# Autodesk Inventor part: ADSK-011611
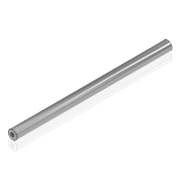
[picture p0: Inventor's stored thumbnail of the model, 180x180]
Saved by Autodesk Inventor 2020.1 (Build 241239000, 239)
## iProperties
Created: 2000-02
Part Number: ADSK-011611
Material: Pearson DGP
Document SubType Name: Modeling
Designer: sspink
Density: 7.83 g/cm^3
Appearance: Chrom - poliert
Mass: 1572.14 g
Surface Area: 359.989 cm^2
Volume: 200.785 cm^3
Control State: 0
Checked Out: False
Master: False
Shininess: 60.0
Length Units: 11269
Angle Units: 11279
Time Units: 11290
Mass Units: 11283
Length Display Precision: 3
Angle Display Precision: 2
Compacted: True
Cutlength: 23.25
Material Desc: Material Description goes here
Material_Number: Pearson
Dimensions: 25x420x25 mm
Mass: 1,572 kg
DocNumber: ADSK-011611.ipt
Folder: 01 - Themengebiete\Simplification\01 - Packaging machine\
VDS_Category: 3D Komponenten
VLT_Material: Pearson DGP
Density: 7.83
Volumn: 204.48056223073252
Area: 356.691416726128
PropertySet Name: Model Information
Author: sspink
Revision Number: -
Title: shaft
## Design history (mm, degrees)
node "Solide1"
  node "Extrusion1" dims "d1" = 420, "d2" = 0
  node "Hole1" dims "d3" = 10.106, "d4" = 9.525, "d5" = 6.35, "d6" = 60 deg, "d7" = 32.3, "d8" = 118 deg, "d21" = 24
  node "Hole2" dims "d9" = 10.106, "d10" = 9.525, "d11" = 6.35, "d12" = 60 deg, "d13" = 32.3, "d14" = 118 deg, "d22" = 24
  node "Chamfer1" dims "d15" = 1, "d16" = 45 deg, "d19" = 1
sketch "Sketch1"
  geometry: C1 r 12.5 at (0, 0); 1 further point
  constraints: 1 centre point, 1 coincident
  dimensions: "d0" = 25 diameter of C1
node "Corps solides"
node "Corps surfaciques"
sketch "Sketch2"
  geometry: C1 r 12.5 at (0, 0) reference; 1 further point
  constraints: 1 coincident
sketch "Sketch3"
  geometry: C1 r 12.5 at (0, 0) reference; 1 further point
  constraints: 1 coincident
